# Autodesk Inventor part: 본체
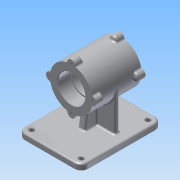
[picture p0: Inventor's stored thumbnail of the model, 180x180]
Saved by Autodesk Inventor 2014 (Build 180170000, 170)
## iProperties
Created: 2015-12
Part Number: 본체
Material: 알루미늄 6061
Document SubType Name: Modeling
Designer: net
Density: 2.71 g/cm^3
Appearance: 알루미늄 - 평지
Mass: 1164.59 g
Surface Area: 814.916 cm^2
Volume: 429.737 cm^3
Author: net
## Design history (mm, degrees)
sketch "스케치4"
  geometry: L1 (-42.5, 0)-(42.5, 0); L2 (42.5, 0)-(42.5, 37); L3 (-26.809, 37)-(-42.5, 37); L4 (-42.5, 37)-(-42.5, 0); L5 (26.809, 37)-(42.5, 37); L6 (-26.809, 37)-(26.809, 37); L7 (-42.5, 23.5)-(-20.8, 23.5); L8 (-20.5, 23.2)-(-20.5, 0); L9 (42.5, 23.5)-(20.8, 23.5); L10 (20.5, 23.2)-(20.5, 0); L11 (20.5, 21)-(-20.5, 21); A1 r 0.3 centre (-20.8, 23.2) between (-20.5, 23.2) and (-20.8, 23.5); A2 r 0.3 centre (20.8, 23.2) between (20.8, 23.5) and (20.5, 23.2); 3 further points
  constraints: 22 end point, 6 horizontal, 6 point on line, 4 point on circle, 4 tangent, 4 vertical, 2 centre point, 2 midpoint, 1 coincident, 1 equal radius, 1 vertical alignment
  dimensions: "d19" = 85 distance between parallel lines of L2 L4; "d20" = 74 diameter of L3 L1; "d21" = 74 diameter of L5 L1; "d22" = 42 diameter of L11 L1; "d23" = 47 diameter of L7 L1; "d24" = 47 diameter of L9 L1; "d25" = 22 distance between parallel lines of L2 L10; "d26" = 22 distance between parallel lines of L4 L8; "d27" = 0.3 radius of A1
revolve "회전1" stored, may be unused: angle "d28" = 90 deg
revolve "회전2" stored, may be unused: angle "d29" = 90 deg
sketch "스케치6"
  geometry: L1 (-42.5, 37)-(42.5, 37) reference; L2 (-42.5, -37)-(-42.5, 37) reference; L3 (42.5, -37)-(42.5, 37) reference; L4 (-42.5, 37)-(42.5, 37); L5 (-42.5, 37)-(-42.5, 44); L6 (-42.5, 44)-(-30.048, 44); L7 (-30.048, 44)-(-27.5, 37); L8 (42.5, 37)-(42.5, 44); L9 (42.5, 44)-(30.048, 44); L10 (30.048, 44)-(27.5, 37); 1 further point
  constraints: 14 end point, 3 horizontal, 2 point on line, 2 vertical
  dimensions: "d32" = 14 diameter of L6 L1; "d33" = 14 diameter of L9 L1; "d34" = 110 deg angle of L1 L10; "d35" = 110 deg angle of L1 L7; "d36" = 15 distance from line of L10.end L8; "d37" = 15 distance from line of L5 L7.end
revolve "회전3" sketch "스케치6" stored, may be unused: angle "d38" = 90 deg
fillet "모깎기3" dims "d39" = 3
fillet "모깎기5" dims "d44" = 3
fillet "모깎기6" dims "d45" = 3
fillet "모깎기7" dims "d46" = 3
hole "구멍2" diameter "d49" = 3.242; stored, may be unused: countersink angle "d53" = 90 deg, drill point angle "d55" = 118 deg; dims "d47" = 10, "d48" = 10, "d50" = 9, "d51" = 4, "d52" = 2, "d54" = 11
chamfer "모따기1" distance "d59" = 1; stored, may be unused: second distance "d60" = 2, angle "d61" = 45 deg
chamfer "모따기2" distance "d62" = 1; stored, may be unused: second distance "d63" = 2, angle "d64" = 45 deg
node "작업 평면1"
sketch "스케치8"
  geometry: L1 (-55, -80)-(55, -80); L2 (55, -80)-(55, 60); L3 (55, 60)-(-55, 60); L4 (-55, 60)-(-55, -80); 1 further point
  constraints: 8 end point, 2 horizontal, 1 perpendicular, 1 vertical
  dimensions: "d66" = 110 distance of L1.start L1.end; "d67" = 140 distance of L1.end L2.end; "d68" = 80 distance from line of L1 point (0, 0); "d69" = 55 distance from line of point (0, 0) L4
extrude "돌출3" join sketch "스케치8" distance "d70" = 10; taper "d71" = 0 deg
fillet "모깎기8" dims "d72" = 12
fillet "모깎기9" dims "d73" = 3
sketch "스케치9"
  geometry: A1 r 9 centre (43, -68) between (43, -77) and (52, -68) reference; A2 r 9 centre (43, 48) between (52, 48) and (43, 57) reference; A3 r 9 centre (-43, 48) between (-43, 57) and (-52, 48) reference; A4 r 9 centre (-43, -68) between (-52, -68) and (-43, -77) reference; 1 further point
hole "구멍3" sketch "스케치9" at (-43, -68), (43, -68), (43, 48), (-43, 48) diameter "d77" = 8; stored, may be unused: countersink angle "d81" = 90 deg, drill point angle "d83" = 0 deg; dims "d78" = 9, "d79" = 4, "d80" = 2, "d82" = 30
chamfer "모따기3" distance "d84" = 1; stored, may be unused: second distance "d85" = 2, angle "d86" = 45 deg
chamfer "모따기4" distance "d87" = 1; stored, may be unused: second distance "d88" = 2, angle "d89" = 45 deg
sketch "스케치10"
  geometry: L1 (-37, -4)-(-37, 4); L2 (37, 4)-(37, -4); L3 (-6, 25)-(6, 25); L4 (6, -25)-(-6, -25); L5 (-6, -25)-(-6, -4); L6 (-6, 4)-(-6, 25); L7 (-37, 4)-(-6, 4); L8 (6, 4)-(37, 4); L9 (6, 25)-(6, 4); L10 (6, -4)-(6, -25); L11 (37, -4)-(6, -4); L12 (-6, -4)-(-37, -4); L13 (6, 4)-(-6, 4); L14 (-6, -4)-(6, -4); 9 further points
  constraints: 28 end point, 7 horizontal, 5 vertical, 4 horizontal alignment, 4 midpoint, 4 perpendicular, 4 vertical alignment
  dimensions: "d96" = 74 distance of L2.end L1.start; "d97" = 8 distance of L1.start L1.end; "d98" = 50 distance between parallel lines of L4 L3; "d99" = 12 distance of L4.start L4.end
sketch "스케치11"
  geometry: L1 (0, 0)-(-32.349, 32.349); L2 (0, 0)-(-68.523, 0); A1 r 37 centre (0, 0) between (-9.104, 35.863) and (-35.863, 9.104) reference; 1 further point
  constraints: 4 end point, 1 horizontal
  dimensions: "d106" = 45 deg angle of L2 L1
extrude "돌출6" join sketch "스케치10" stored distance "d113" = 10; taper "d114" = 0 deg
sketch "스케치13"
  geometry: L1 (48, -70)-(-68, -70) reference; L2 (-25, -70)-(-20.948, -37); L3 (20.948, -37)-(25, -70); L4 (-68, -70)-(48, -70) reference; L5 (0, -70)-(0, -37); L6 (0, -70)-(-25, -70); L7 (25, -70)-(0, -70); L8 (-20.948, -37)-(-19.876, -28.27); L9 (20.948, -37)-(19.876, -28.27); L10 (19.876, -28.27)-(-19.876, -28.27); 1 further point
  constraints: 16 end point, 3 horizontal, 3 point on line, 2 collinear, 1 vertical
  dimensions: "d115" = 25 horizontal distance of point (0, 0) L2.start; "d116" = 25 horizontal distance of point (0, 0) L3.end; "d117" = 97 deg angle of L1 L3; "d118" = 97 deg angle of L1 L2
extrude "돌출7" join sketch "스케치13" stored distance "d119" = 12; taper "d120" = 0 deg
node "작업 평면3"
sketch "스케치14"
  geometry: L1 (-42.5, -18.921)-(-42.5, 18.921) reference; 2 further points
  constraints: 1 coincident, 1 other
  dimensions: "d121" = 42.5 distance from line of L1 point (0, 0) (derived)
feature "엠보싱2" sketch "스케치14" dims "d19" = 85, "d20" = 74, "d21" = 74, "d22" = 42, "d23" = 47, "d24" = 47, "d25" = 22, "d26" = 22, "d27" = 0.3, "d29" = 90 deg, "d122" = 0.5, "d123" = 0
fillet "모깎기14" dims "d132" = 3
fillet "모깎기17" dims "d135" = 3
fillet "모깎기18" dims "d136" = 3
fillet "모깎기19" dims "d137" = 3
fillet "모깎기20" dims "d138" = 3
fillet "모깎기21" dims "d139" = 3
node "솔리드2"
pattern_circular "원형 패턴1" dims angle "d42" = 360 deg
pattern_circular "원형 패턴2" dims angle "d57" = 360 deg
mirror "대칭1"
